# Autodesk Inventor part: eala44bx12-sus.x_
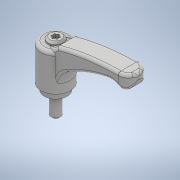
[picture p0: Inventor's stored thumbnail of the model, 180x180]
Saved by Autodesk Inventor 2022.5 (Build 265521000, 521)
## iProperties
Created: 2018-05
Part Number: eala44bx12-sus.x_
Material: 一般
Document SubType Name: Modeling
Designer: imaocorp
Density: 1 g/cm^3
Appearance: 既定
Sending System: SOLIDWORKS 2016-2016286
MC: AMD64
MC_MODEL: AMD64 Family 21 Model 2 Stepping 0, AuthenticAMD
OS: Windows_NT
FRU: Parasolid Version 28.0, build 224,  7-29-2016
FORMAT: text
GUISE: transmit
KEY: eala44bx12-sus
FILE: eala44bx12-sus.x_t
DATE: Fri May 18 11:28:03 2018
Author: imaocorp
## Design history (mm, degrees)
feature "Base1"
node "ソリッド1"
